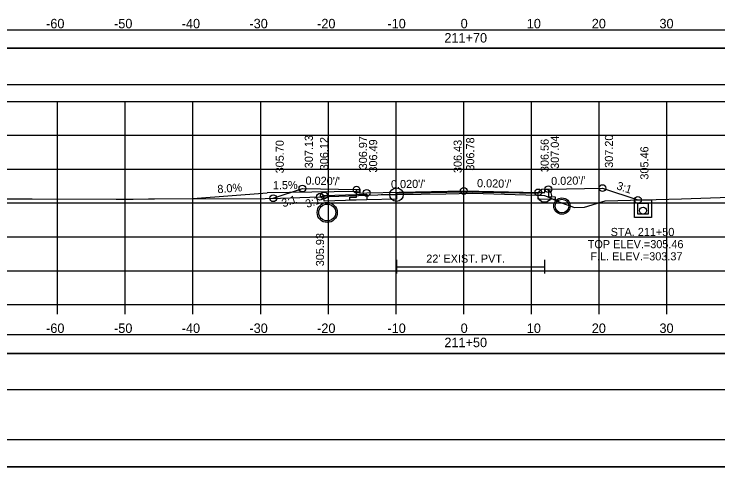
# Model space of a CAD drawing. Extents: x 1370538 to 1372872, y 376220 to 381127.
# Drawn here: x 1370642.2 to 1370746.2, y 379481.3 to 379548.2 of the extents above; entities that cross this region are included whole.
import ezdxf

# ---------------------------------------------------------------- set-up
doc = ezdxf.new("R2010")
doc.units = 0
for name, color, linetype in [('R_Border', 7, 'Continuous'), ('R_Border Notes', 7, 'Continuous'), ('R_Border PE', 7, 'Continuous'), ('R_Border Prem', 7, 'Continuous'), ('R_Dimension', 7, 'Continuous'), ('R_Fin Surface', 7, 'Continuous'), ('R_Grid', 7, 'Continuous'), ('R_Horz Alg Annot', 7, 'Continuous'), ('R_No Plot', 7, 'Continuous'), ('R_Water', 7, 'Continuous'), ('R_Water Annot', 7, 'Continuous'), ('R_Xsect Elev', 7, 'Continuous'), ('R_Xsect Slope', 7, 'Continuous'), ('T_Detection Zones', 7, 'Continuous')]:
    doc.layers.add(name, color=color, linetype=linetype)

msp = doc.modelspace()

# ---------------------------------------------------------------- linework, layer by layer
at = {"layer": 'R_Border'}
for p, q in [((1370698.68, 379511.87), (1370698.68, 379509.87)), ((1370720.55, 379511.87), (1370720.55, 379509.87)), ((1370698.68, 379510.87), (1370720.55, 379510.87))]:
    msp.add_line(p, q, dxfattribs=at)
for points in [[(1370708.61, 379521.9), (1370698.68, 379521.7), (1370698.68, 379520.86), (1370694.27, 379520.78), (1370691.77, 379520.73), (1370691.77, 379521.15), (1370692.77, 379521.17), (1370692.77, 379522.26)], [(1370721.11, 379522.33), (1370721.11, 379521.23), (1370722.11, 379521.21), (1370722.11, 379520.8), (1370719.61, 379520.85), (1370719.61, 379520.84), (1370719.61, 379521.68), (1370708.61, 379521.9)]]:
    msp.add_lwpolyline(points, dxfattribs=at)
at = {"layer": 'R_Border Notes'}
msp.add_line((1370866.79, 379485.29), (1370550.61, 379485.29), dxfattribs=at)
at = {"layer": 'R_Border Prem'}
for p, q in [((1370558.61, 379505.29), (1370858.61, 379505.29)), ((1370648.61, 379503.89), (1370648.61, 379505.29)), ((1370658.61, 379503.89), (1370658.61, 379505.29)), ((1370668.61, 379503.89), (1370668.61, 379505.29)), ((1370678.61, 379503.89), (1370678.61, 379505.29)), ((1370688.61, 379503.89), (1370688.61, 379505.29)), ((1370698.61, 379503.89), (1370698.61, 379505.29)), ((1370708.61, 379503.89), (1370708.61, 379505.29)), ((1370718.61, 379503.89), (1370718.61, 379505.29)), ((1370728.61, 379503.89), (1370728.61, 379505.29)), ((1370738.61, 379503.89), (1370738.61, 379505.29))]:
    msp.add_line(p, q, dxfattribs=at)
at = {"layer": 'R_Dimension'}
msp.add_lwpolyline([(1370638.13, 379520.89), (1370643.42, 379520.88), (1370644.83, 379520.89), (1370657.27, 379520.86), (1370657.38, 379520.86), (1370659.77, 379520.87), (1370662.06, 379520.92), (1370662.93, 379520.92), (1370679.29, 379520.96), (1370681.54, 379521.01), (1370695.91, 379521.5), (1370696.42, 379521.52), (1370697.48, 379521.53), (1370698.68, 379521.53), (1370705.96, 379521.66), (1370709.88, 379521.74), (1370719.36, 379521.43), (1370720.55, 379521.39), (1370720.67, 379521.37), (1370723.03, 379520.31), (1370724.96, 379519.64), (1370726.44, 379519.67), (1370729.52, 379520.63), (1370740.77, 379520.89), (1370747.9, 379521.14)], dxfattribs=at)
at = {"layer": 'R_Fin Surface'}
for points in [[(1370680.47, 379520.99), (1370684.77, 379522.42), (1370692.77, 379522.26), (1370693.27, 379522.26), (1370693.27, 379521.76), (1370694.27, 379521.78), (1370708.61, 379522.07)], [(1370708.61, 379522.07), (1370719.61, 379521.85), (1370720.61, 379521.83), (1370720.61, 379522.33), (1370721.11, 379522.33), (1370729.11, 379522.49), (1370734.34, 379520.74)]]:
    msp.add_lwpolyline(points, dxfattribs=at)
at = {"layer": 'R_Grid'}
for p, q in [((1370558.61, 379535.29), (1370858.61, 379535.29)), ((1370558.61, 379535.29), (1370858.61, 379535.29)), ((1370648.61, 379505.29), (1370648.61, 379535.29)), ((1370648.61, 379505.29), (1370648.61, 379535.29)), ((1370658.61, 379505.29), (1370658.61, 379535.29)), ((1370658.61, 379505.29), (1370658.61, 379535.29)), ((1370668.61, 379505.29), (1370668.61, 379535.29)), ((1370668.61, 379505.29), (1370668.61, 379535.29)), ((1370678.61, 379505.29), (1370678.61, 379535.29)), ((1370678.61, 379505.29), (1370678.61, 379535.29)), ((1370688.61, 379505.29), (1370688.61, 379535.29)), ((1370688.61, 379505.29), (1370688.61, 379535.29)), ((1370698.61, 379505.29), (1370698.61, 379535.29)), ((1370698.61, 379505.29), (1370698.61, 379535.29)), ((1370708.61, 379505.29), (1370708.61, 379535.29)), ((1370708.61, 379505.29), (1370708.61, 379535.29)), ((1370718.61, 379505.29), (1370718.61, 379535.29)), ((1370718.61, 379505.29), (1370718.61, 379535.29)), ((1370728.61, 379505.29), (1370728.61, 379535.29)), ((1370728.61, 379505.29), (1370728.61, 379535.29)), ((1370738.61, 379505.29), (1370738.61, 379535.29)), ((1370738.61, 379505.29), (1370738.61, 379535.29)), ((1370558.61, 379530.29), (1370858.61, 379530.29)), ((1370558.61, 379530.29), (1370858.61, 379530.29)), ((1370558.61, 379525.29), (1370858.61, 379525.29)), ((1370558.61, 379525.29), (1370858.61, 379525.29)), ((1370558.61, 379520.29), (1370858.61, 379520.29)), ((1370558.61, 379520.29), (1370858.61, 379520.29)), ((1370558.61, 379515.29), (1370858.61, 379515.29)), ((1370558.61, 379515.29), (1370858.61, 379515.29)), ((1370558.61, 379510.29), (1370858.61, 379510.29)), ((1370558.61, 379510.29), (1370858.61, 379510.29)), ((1370558.61, 379505.29), (1370858.61, 379505.29)), ((1370558.61, 379505.29), (1370858.61, 379505.29))]:
    msp.add_line(p, q, dxfattribs=at)
at = {"layer": 'R_Horz Alg Annot'}
for points in [[(1370687.37, 379521.21), (1370687.97, 379521.41), (1370694.27, 379521.61)], [(1370694.27, 379521.61), (1370694.27, 379520.78), (1370687.97, 379520.58), (1370687.97, 379521.41)]]:
    msp.add_lwpolyline(points, dxfattribs=at)
at = {"layer": 'R_No Plot'}
msp.add_line((1370538.21, 379481.31), (1370871.54, 379481.31), dxfattribs=at)
for points in [[(1370538.2, 379694.64), (1370871.54, 379694.64), (1370871.54, 379481.3), (1370538.2, 379481.3)], [(1370784.53, 379690.75), (1370784.53, 379680.87), (1370820.26, 379680.87), (1370820.26, 379677.95), (1370843.46, 379677.95), (1370843.46, 379653.61), (1370866.79, 379653.61), (1370866.79, 379485.29), (1370550.61, 379485.29), (1370550.61, 379690.75)]]:
    msp.add_lwpolyline(points, close=True, dxfattribs=at)
for centre, radius in [((1370729.11, 379522.49), 0.5), ((1370684.77, 379522.42), 0.5), ((1370687.97, 379521.41), 0.5), ((1370692.77, 379522.26), 0.5), ((1370694.27, 379521.78), 0.5), ((1370698.68, 379521.53), 1), ((1370708.61, 379522.07), 0.5), ((1370708.61, 379522.07), 0.5), ((1370719.61, 379521.85), 0.5), ((1370720.55, 379521.39), 1), ((1370721.11, 379522.33), 0.5), ((1370680.47, 379520.99), 0.5), ((1370687.37, 379521.21), 0.5), ((1370723.11, 379519.83), 1.21), ((1370734.34, 379520.74), 0.5), ((1370688.44, 379518.89), 1.48), ((1370735.09, 379519.16), 0.505)]:
    msp.add_circle(centre, radius, dxfattribs=at)
at = {"layer": 'R_Water'}
for p, q in [((1370692.77, 379522.01), (1370679.59, 379521.81)), ((1370693.27, 379521.76), (1370692.77, 379522.01)), ((1370668.61, 379520.93), (1370679.59, 379521.81))]:
    msp.add_line(p, q, dxfattribs=at)
for points in [[(1370735.09, 379520.74), (1370736.34, 379520.74), (1370736.34, 379518.16), (1370735.09, 379518.16), (1370733.84, 379518.16), (1370733.84, 379520.74)], [(1370735.09, 379520.24), (1370735.84, 379520.24), (1370735.84, 379518.66), (1370735.09, 379518.66), (1370734.34, 379518.66), (1370734.34, 379520.24)]]:
    msp.add_lwpolyline(points, close=True, dxfattribs=at)
for centre, radius in [((1370688.44, 379518.89), 1.25), ((1370723.11, 379519.83), 1), ((1370735.09, 379519.16), 0.5)]:
    msp.add_circle(centre, radius, dxfattribs=at)
at = {"layer": 'R_Xsect Elev'}
msp.add_line((1370708.61, 379521.71), (1370708.61, 379531.71), dxfattribs=at)
at = {"layer": 'T_Detection Zones'}
for points in [[(1370550.96, 379543.14), (1370866.09, 379543.14), (1370866.09, 379545.84), (1370550.96, 379545.84)], [(1370550.96, 379537.81), (1370866.09, 379537.81), (1370866.09, 379543.14), (1370550.96, 379543.14)], [(1370550.96, 379498.08), (1370866.09, 379498.08), (1370866.09, 379500.79), (1370550.96, 379500.79)], [(1370550.96, 379492.76), (1370866.09, 379492.76), (1370866.09, 379498.08), (1370550.96, 379498.08)]]:
    msp.add_lwpolyline(points, close=True, dxfattribs=at)

# ---------------------------------------------------------------- texts
at = {"layer": 'R_Border PE'}
for s, p in [('-60', (1370646.91, 379546.09)), ('-50', (1370656.95, 379546.09)), ('-40', (1370666.95, 379546.09)), ('-30', (1370676.95, 379546.09)), ('-20', (1370686.95, 379546.09)), ('-10', (1370697.34, 379546.09)), ('0', (1370708.15, 379546.09)), ('10', (1370717.92, 379546.09)), ('20', (1370727.52, 379546.09)), ('30', (1370737.52, 379546.09)), ('211+70', (1370705.75, 379543.99)), ('-60', (1370646.91, 379501.09)), ('-50', (1370656.95, 379501.09)), ('-40', (1370666.95, 379501.09)), ('-30', (1370676.95, 379501.09)), ('-20', (1370686.95, 379501.09)), ('-10', (1370697.34, 379501.09)), ('0', (1370708.15, 379501.09)), ('10', (1370717.92, 379501.09)), ('20', (1370727.52, 379501.09)), ('30', (1370737.52, 379501.09)), ('211+50', (1370705.75, 379498.99))]:
    msp.add_text(s, height=1.4, dxfattribs=at).set_placement(p)
at = {"layer": 'R_Water'}
msp.add_text("22' EXIST. PVT.", height=1.2, dxfattribs=at).set_placement((1370703.07, 379511.47))
at = {"layer": 'R_Water Annot'}
for s, p in [('STA. 211+50', (1370730.31, 379515.41)), ('TOP ELEV.=305.46', (1370726.93, 379513.61)), ('F.L. ELEV.=303.37', (1370727.31, 379511.81))]:
    msp.add_text(s, height=1.2, dxfattribs=at).set_placement(p)
at = {"layer": 'R_Xsect Elev'}
for s, rotation, p in [('307.13', 90, (1370686.32, 379525.42)), ('307.20', 90, (1370730.66, 379525.49)), ('305.70', 90, (1370682.02, 379524.67)), ('306.12', 90, (1370688.57, 379525.12)), ('306.97', 90, (1370694.32, 379525.26)), ('306.49', 90, (1370695.82, 379524.78)), ('306.43', 90, (1370708.31, 379524.71)), ('306.78', 90, (1370710.16, 379525.07)), ('306.56', 90, (1370721.16, 379524.85)), ('307.04', 90, (1370722.66, 379525.33)), ('305.46', 90, (1370735.89, 379523.74)), ('8.0%', 4.5739, (1370672.26, 379521.73)), ('1.5%', 0.8594, (1370680.42, 379522.31)), ('305.93', 90, (1370687.97, 379510.94))]:
    msp.add_text(s, height=1.2, rotation=rotation, dxfattribs=at).set_placement(p)
at = {"layer": 'R_Xsect Slope'}
for s, rotation, p in [("0.020'/'", 358.8542, (1370685.22, 379523.01)), ("0.020'/'", 1.1458, (1370721.53, 379522.93)), ("0.020'/'", 1.1458, (1370697.87, 379522.45)), ("0.020'/'", 358.8542, (1370710.56, 379522.63)), ('3:1', 341.5651, (1370731.09, 379522.35)), ('3:1', 18.4349, (1370681.94, 379519.64)), ('3:1', 18.4332, (1370685.45, 379519.55))]:
    msp.add_text(s, height=1.2, rotation=rotation, dxfattribs=at).set_placement(p)

doc.saveas('drawing.dxf')
